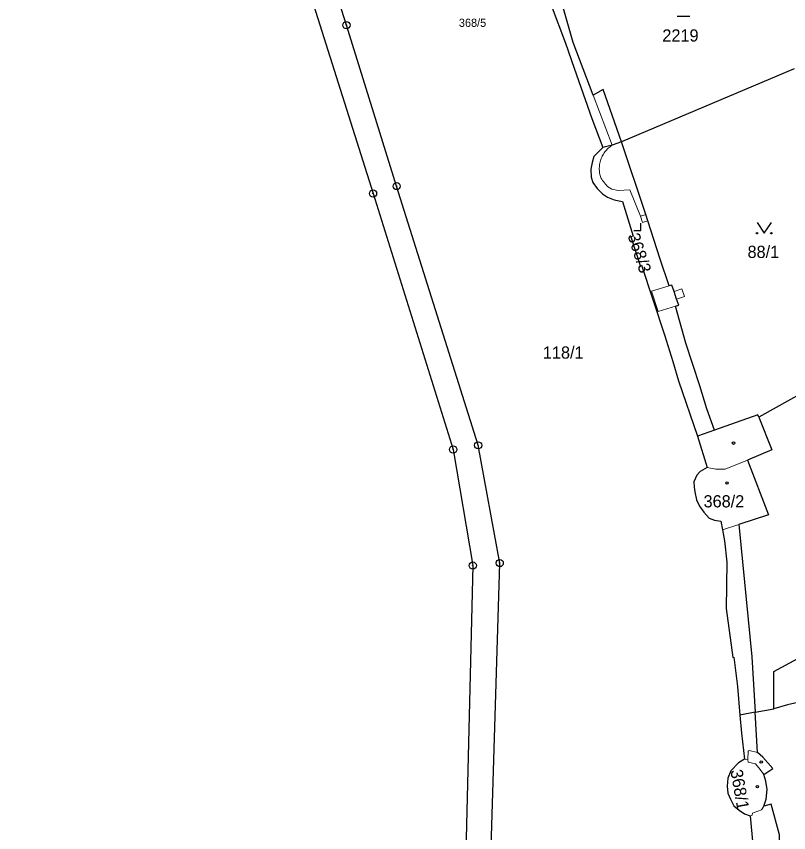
# Model space of a CAD drawing. Extents: x -679733 to -673243, y -1075091 to -1066557.
# Drawn here: x -676651.2 to -676543.4, y -1071761.5 to -1071647.5 of the extents above; entities that cross this region are included whole.
import ezdxf
from ezdxf.enums import TextEntityAlignment as Align

# ---------------------------------------------------------------- set-up
doc = ezdxf.new("R2010")
doc.units = 0
doc.header["$LTSCALE"] = 0.68
for name, color, linetype, lineweight in [('1', 7, 'Continuous', 25), ('3', 7, 'Continuous', 25), ('4', 7, 'Continuous', 13), ('5', 7, 'Continuous', 25), ('8', 7, 'Continuous', 25)]:
    doc.layers.add(name, color=color, linetype=linetype, lineweight=lineweight)
doc.layers.add('2', color=7, linetype='Continuous')

msp = doc.modelspace()

# ---------------------------------------------------------------- linework, layer by layer
at = {"layer": '1'}
for p, q in [((-676542.65, -1071654.84), (-676566.76, -1071665.06)), ((-676548.11, -1071744.66), (-676550.25, -1071745.06)), ((-676548.11, -1071744.66), (-676545.53, -1071744.17))]:
    msp.add_line(p, q, dxfattribs=at)
for points in [[(-676651.25, -1071520.53), (-676649.67, -1071525.28), (-676636.33, -1071567.59), (-676632.67, -1071580.29), (-676618.91, -1071616.92), (-676601.45, -1071672.26), (-676590.27, -1071707.98), (-676587.53, -1071724.18), (-676588.53, -1071766.09), (-676588.57, -1071776.49), (-676583.64, -1071788.99), (-676568.69, -1071809.98), (-676555.21, -1071828.53), (-676552.27, -1071835.54), (-676544.88, -1071865.16), (-676535.44, -1071910.25), (-676533.59, -1071921.04), (-676532.8, -1071927.61), (-676534.01, -1071935.8), (-676540.25, -1071959.64), (-676548.46, -1071989.23), (-676550.64, -1071999.75), (-676548.02, -1072010.25), (-676541.89, -1072018.69)], [(-676541.48, -1071865.21), (-676541.59, -1071864.65), (-676541.5, -1071864.22), (-676548.91, -1071834.51), (-676552.17, -1071826.9), (-676565.68, -1071808.28), (-676580.41, -1071787.4), (-676585.19, -1071776.11), (-676585.04, -1071766.54), (-676583.77, -1071723.83), (-676586.78, -1071707.4), (-676598.16, -1071671.22), (-676605.17, -1071648.76), (-676615.61, -1071615.91), (-676621.57, -1071599.95), (-676629.42, -1071579.1), (-676632.27, -1071569.47)], [(-676566.76, -1071665.06), (-676569.31, -1071657.76), (-676570.75, -1071658.51), (-676573.53, -1071651.2), (-676575.18, -1071645.34), (-676578.9, -1071633.97), (-676580.28, -1071634.6)], [(-676580.28, -1071634.6), (-676580.21, -1071634.74), (-676581.74, -1071635.81), (-676582.11, -1071636.36), (-676582.52, -1071637.81), (-676582.29, -1071638.93), (-676581.89, -1071639.9), (-676581.5, -1071640.44), (-676579.97, -1071641.35), (-676578.05, -1071641.43), (-676576.57, -1071645.99), (-676574.59, -1071651.29), (-676573.38, -1071654.77), (-676570.92, -1071661.77), (-676569.37, -1071665.85)], [(-676566.76, -1071665.06), (-676568.08, -1071665.53), (-676569.37, -1071665.85)], [(-676553.79, -1071705.28), (-676554.85, -1071702.3), (-676555.86, -1071699.1), (-676557.79, -1071693.15), (-676559.24, -1071687.97), (-676558.79, -1071687.85), (-676559.08, -1071686.98), (-676559.44, -1071685.91), (-676559.73, -1071685.04), (-676560.13, -1071685.15), (-676561.36, -1071681.42), (-676563.08, -1071676.06), (-676563.36, -1071675.2), (-676566.76, -1071665.06)], [(-676569.37, -1071665.85), (-676570.04, -1071666.47), (-676570.62, -1071667.09), (-676570.88, -1071667.92), (-676571.06, -1071668.85), (-676571.01, -1071669.97), (-676570.77, -1071670.73), (-676570.19, -1071671.57), (-676569.44, -1071672.28), (-676568.71, -1071672.75), (-676567.81, -1071673.15), (-676566.65, -1071673.35), (-676565.13, -1071678.22), (-676565.48, -1071678.31), (-676564.15, -1071682.32), (-676563.97, -1071682.27), (-676560.75, -1071691.99), (-676559.62, -1071695.72), (-676558.82, -1071698.41), (-676556.14, -1071706.13)], [(-676521.43, -1071684.04), (-676521.096, -1071684.542), (-676520.849, -1071685.093), (-676520.697, -1071685.677), (-676520.643, -1071686.278), (-676520.664, -1071686.69), (-676520.777, -1071687.282), (-676520.988, -1071687.848), (-676521.288, -1071688.371), (-676521.671, -1071688.837), (-676522.126, -1071689.234), (-676522.64, -1071689.55), (-676547.6, -1071703.46)], [(-676547.6, -1071703.46), (-676547.73, -1071703.14), (-676553.79, -1071705.28), (-676556.14, -1071706.13)], [(-676547.6, -1071703.46), (-676545.78, -1071708.03), (-676549.2, -1071709.47), (-676546.26, -1071717.09), (-676550.38, -1071718.44), (-676548.57, -1071736.9), (-676548.11, -1071744.66)], [(-676556.14, -1071706.13), (-676554.82, -1071710.5), (-676555.81, -1071711.06), (-676556.24, -1071711.57), (-676556.67, -1071712.49), (-676556.65, -1071713.23), (-676556.55, -1071713.87), (-676556.31, -1071715), (-676555.88, -1071715.9), (-676555.3, -1071716.71), (-676554.55, -1071717.57), (-676553.79, -1071717.85), (-676552.89, -1071717.99), (-676552.68, -1071719.2), (-676552.41, -1071720.75), (-676552.05, -1071723.7), (-676552.17, -1071730.19), (-676551.25, -1071737.02), (-676551.1, -1071736.98), (-676550.6, -1071741.04), (-676550.25, -1071745.06)], [(-676545.53, -1071744.17), (-676545.5, -1071738.97), (-676530.97, -1071731.11)], [(-676530.24, -1071740.39), (-676530.99, -1071740.6), (-676530.9, -1071740.74), (-676535.27, -1071741.75), (-676543.58, -1071743.61), (-676545.53, -1071744.17)], [(-676545.3, -1071767.07), (-676544.83, -1071766.03), (-676544.69, -1071764.65), (-676544.71, -1071761.74), (-676545.87, -1071757.48), (-676546.91, -1071757.76), (-676546.6, -1071756.76), (-676546.44, -1071755.43), (-676546.64, -1071754.29), (-676546.91, -1071753.36), (-676545.63, -1071752.49), (-676547.03, -1071750.92), (-676547.77, -1071750.28), (-676548.11, -1071744.66)], [(-676550.25, -1071745.06), (-676550.04, -1071747.55), (-676549.61, -1071751.21), (-676550.45, -1071751.73), (-676551.5, -1071752.85), (-676551.94, -1071753.87), (-676552.01, -1071754.95), (-676551.92, -1071755.96), (-676551.56, -1071756.76), (-676551.1, -1071757.72), (-676550.35, -1071758.31), (-676549.62, -1071758.81), (-676548.81, -1071759.13), (-676548.07, -1071767.18), (-676547.85, -1071767.97)]]:
    msp.add_lwpolyline(points, dxfattribs=at)
at = {"layer": '3'}
msp.add_line((-676558.993, -1071647.53), (-676557.243, -1071647.53), dxfattribs=at)
for points in [[(-676565.071, -1071677.41), (-676564.07, -1071677.41), (-676564.07, -1071676.41)], [(-676547.85, -1071676.299), (-676546.85, -1071677.8), (-676545.85, -1071676.299)]]:
    msp.add_lwpolyline(points, dxfattribs=at)
for centre in [(-676547.85, -1071677.7995), (-676545.85, -1071677.7995)]:
    msp.add_circle(centre, 0.1, dxfattribs=at)
at = {"layer": '4'}
for p, q in [((-676568.08, -1071665.53), (-676570.75, -1071658.51)), ((-676568.12, -1071671.67), (-676568.72, -1071671.26)), ((-676567.22, -1071671.85), (-676568.12, -1071671.67)), ((-676567.22, -1071671.85), (-676565.59, -1071671.73)), ((-676565.59, -1071671.73), (-676564.14, -1071675.42)), ((-676564.14, -1071675.42), (-676563.36, -1071675.2)), ((-676564.14, -1071675.42), (-676563.86, -1071676.3)), ((-676563.86, -1071676.3), (-676563.08, -1071676.06)), ((-676560.13, -1071685.15), (-676562.59, -1071685.9)), ((-676559.44, -1071685.91), (-676558.35, -1071685.55)), ((-676558.35, -1071685.55), (-676557.99, -1071686.62)), ((-676561.64, -1071688.74), (-676562.59, -1071685.9)), ((-676557.99, -1071686.62), (-676559.08, -1071686.98)), ((-676559.24, -1071687.97), (-676561.64, -1071688.74)), ((-676552.3, -1071710.73), (-676549.2, -1071709.47)), ((-676553.6, -1071710.73), (-676554.82, -1071710.5)), ((-676552.3, -1071710.73), (-676553.6, -1071710.73)), ((-676552.68, -1071719.2), (-676550.38, -1071718.44)), ((-676549.11, -1071750.06), (-676549.13, -1071751.25)), ((-676548.97, -1071749.99), (-676549.11, -1071750.06)), ((-676547.77, -1071750.28), (-676548.97, -1071749.99)), ((-676549.61, -1071751.21), (-676549.13, -1071751.25)), ((-676549.13, -1071751.25), (-676549.07, -1071751.61)), ((-676549.07, -1071751.61), (-676548.08, -1071751.85)), ((-676548.08, -1071751.85), (-676547.42, -1071752.66)), ((-676547.42, -1071752.66), (-676546.91, -1071753.36)), ((-676548.27, -1071758.63), (-676548.48, -1071758.74)), ((-676547.21, -1071758.25), (-676548.27, -1071758.63)), ((-676546.91, -1071757.76), (-676547.21, -1071758.25)), ((-676548.51, -1071759.01), (-676548.81, -1071759.13)), ((-676548.48, -1071758.74), (-676548.51, -1071759.01))]:
    msp.add_line(p, q, dxfattribs=at)
for points in [[(-676569.65, -1071670.07), (-676569.704, -1071669.906), (-676569.751, -1071669.739), (-676569.79, -1071669.571), (-676569.822, -1071669.401), (-676569.846, -1071669.23), (-676569.862, -1071669.057), (-676569.871, -1071668.885), (-676569.872, -1071668.712), (-676569.865, -1071668.539), (-676569.85, -1071668.367), (-676569.827, -1071668.195), (-676569.797, -1071668.025), (-676569.759, -1071667.856), (-676569.714, -1071667.689), (-676569.661, -1071667.525), (-676569.601, -1071667.363), (-676569.533, -1071667.203), (-676569.459, -1071667.047), (-676569.378, -1071666.895), (-676569.289, -1071666.746), (-676569.194, -1071666.601), (-676569.093, -1071666.461), (-676568.986, -1071666.326), (-676568.872, -1071666.195), (-676568.753, -1071666.07), (-676568.629, -1071665.95), (-676568.499, -1071665.836), (-676568.364, -1071665.728), (-676568.224, -1071665.626), (-676568.08, -1071665.53)], [(-676569.65, -1071670.07), (-676569.532, -1071670.251), (-676569.409, -1071670.429), (-676569.281, -1071670.603), (-676569.148, -1071670.773), (-676569.01, -1071670.94), (-676568.867, -1071671.102), (-676568.72, -1071671.26)]]:
    msp.add_lwpolyline(points, dxfattribs=at)
at = {"layer": '5'}
for centre in [(-676551.1368, -1071707.0892), (-676552.0368, -1071712.6492), (-676547.2668, -1071751.5892), (-676547.8068, -1071755.0392)]:
    msp.add_circle(centre, 0.175, dxfattribs=at)
at = {"layer": '8'}
for centre, radius in [((-676605.17, -1071648.7599), 0.5), ((-676605.17, -1071648.7599), 0.0303), ((-676598.16, -1071671.2199), 0.5), ((-676601.45, -1071672.2599), 0.5), ((-676598.16, -1071671.2199), 0.0303), ((-676601.45, -1071672.2599), 0.0303), ((-676586.78, -1071707.3999), 0.5), ((-676586.78, -1071707.3999), 0.0303), ((-676590.27, -1071707.9799), 0.5), ((-676590.27, -1071707.9799), 0.0303), ((-676587.53, -1071724.1799), 0.5), ((-676587.53, -1071724.1799), 0.0303), ((-676583.77, -1071723.8299), 0.5), ((-676583.77, -1071723.8299), 0.0303)]:
    msp.add_circle(centre, radius, dxfattribs=at)

# ---------------------------------------------------------------- texts
at = {"layer": '2'}
msp.add_text('368/5', height=1.14, dxfattribs=at).set_placement((-676585.659, -1071648.999), align=Align.RIGHT)
for s, p in [('2219', (-676561.07, -1071651.05)), ('88/1', (-676549.18, -1071681.249)), ('118/1', (-676577.75, -1071695.3)), ('368/2', (-676555.32, -1071716.06))]:
    msp.add_text(s, height=1.7, dxfattribs=at).set_placement(p)
for s, rotation, p in [('368/3', 288, (-676565.938, -1071678.112)), ('368/1', 280, (-676551.577, -1071752.787))]:
    msp.add_text(s, height=1.7, rotation=rotation, dxfattribs=at).set_placement(p)

doc.saveas('drawing.dxf')
